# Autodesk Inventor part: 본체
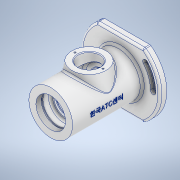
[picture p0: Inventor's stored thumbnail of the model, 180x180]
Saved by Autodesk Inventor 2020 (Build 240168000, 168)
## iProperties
Created: 2022-05
Part Number: 본체
Material: 알루미늄 6061
Document SubType Name: Modeling
Designer: Student
Density: 2.7 g/cm^3
Appearance: 알루미늄 - 평지
Mass: 694.374 g
Surface Area: 622.592 cm^2
Volume: 257.175 cm^3
Author: Student
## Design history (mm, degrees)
sketch "스케치1"
  geometry: L1 (0, 57.5)-(0, -57.5); L2 (32, 57.5)-(32, -44.5); L3 (32, -44.5)-(58, -44.5); L4 (58, -44.5)-(58, -54.5); L5 (58, -54.5)-(36, -54.5); L6 (36, -54.5)-(36, -57.5); L7 (36, -57.5)-(30, -57.5); L8 (30, -57.5)-(20, -43.5); L9 (14.596, -36.2)-(11, -36.2); L10 (11, -36.2)-(11, -33.5); L11 (11, -33.5)-(15, -33.5); L12 (15, -33.5)-(15, -28.5); L13 (15, -28.5)-(17.5, -28.5); L14 (17.5, -28.5)-(17.5, -17.5); L15 (17.5, -17.5)-(27, -17.5); L16 (27, -17.5)-(27, 20.5); L17 (27, 20.5)-(17.5, 20.5); L18 (17.5, 20.5)-(17.5, 31.5); L19 (17.5, 31.5)-(18.5, 31.5); L20 (18.5, 31.5)-(18.5, 33.25); L21 (18.5, 33.25)-(17.5, 33.25); L22 (17.5, 33.25)-(17.5, 35.5); L23 (17.5, 35.5)-(22.5, 35.5); L24 (22.5, 35.5)-(22.5, 46.5); L25 (22.5, 46.5)-(24, 46.5); L26 (24, 46.5)-(24, 49.5); L27 (24, 49.5)-(0, 49.5); L28 (32, 57.5)-(0, 57.5); L29 (14.596, -36.2)-(14.596, -42.8); L30 (14.596, -42.8)-(15, -43.5); L31 (15, -43.5)-(20, -43.5); 3 further points
  constraints: 62 end point, 21 perpendicular, 4 vertical, 2 horizontal, 2 midpoint, 2 point on line, 1 coincident, 1 horizontal alignment
  dimensions: "d0" = 115 distance of L1.start L1.end; "d1" = 64 diameter of L2 L1; "d2" = 116 diameter of L4 L1; "d3" = 72 diameter of L6 L1; "d4" = 60 diameter of L7.end L1; "d5" = 40 diameter of L8.end L1; "d6" = 22 diameter of L10 L1; "d9" = 150 deg angle of L29 L30; "d10" = 0.7 distance from line of L29.end L31; "d11" = 30 diameter of L30.end L1; "d12" = 14 distance between parallel lines of L31 L7; "d13" = 6.6 distance of L9.start L29.end; "d15" = 5 distance from line of L12.end L11; "d16" = 29 distance between parallel lines of L7 L13; "d17" = 11 distance from line of L14.end L13; "d18" = 38 distance from line of L16.end L15; "d19" = 54 diameter of L16 L1; "d20" = 30 diameter of L12 L1; "d21" = 35 diameter of L14 L1; "d22" = 35 diameter of L18 L1; "d23" = 37 diameter of L20 L1; "d24" = 11 distance between parallel lines of L19 L17; "d25" = 1.75 distance between parallel lines of L21 L19; "d26" = 4 distance between parallel lines of L23 L19; "d27" = 45 diameter of L24 L1; "d28" = 22 distance between parallel lines of L28 L23; "d29" = 3 distance between parallel lines of L27 L25; "d30" = 8 distance between parallel lines of L28 L27; "d31" = 48 diameter of L26 L1; "d32" = 13 distance between parallel lines of L3 L7; "d33" = 3 distance between parallel lines of L7 L5
revolve "회전1" sketch "스케치1" stored, may be unused: angle "d34" = 90 deg
sketch "스케치2"
  geometry: C1 r 11 at (0, 0) reference; 2 further points
  constraints: 1 coincident
hole "구멍1" sketch "스케치2" at (0, 0) diameter "d35" = 43.376; stored, may be unused: countersink angle "d39" = 90 deg, drill point angle "d41" = 0 deg; dims "d36" = 8, "d37" = 4, "d38" = 2, "d40" = 10
sketch "스케치3"
  geometry: L1 (-33.985, 47)-(33.985, 47); L2 (33.985, -47)-(-33.985, -47); L3 (0, 47)-(0, -47); A1 r 58 centre (0, 0) between (-33.985, 47) and (33.985, 47) reference; 2 further points
  constraints: 6 end point, 4 point on circle, 3 midpoint, 1 coincident, 1 horizontal, 1 parallel
  dimensions: "d42" = 94 distance between parallel lines of L2 L1
extrude "돌출1" cut sketch "스케치3" distance "d43" = 10; taper "d44" = 0 deg
sketch "스케치4"
  geometry: L1 (33.985, 47)-(-2.785, 16.146); L2 (33.985, 47)-(-14.015, 47); L3 (33.985, 47)-(70.755, 77.854); L4 (33.985, 47)-(81.985, 47); A1 r 48 centre (33.985, 47) between (-14.015, 47) and (-2.785, 16.146); A2 r 52 centre (33.985, 47) between (-18.015, 47) and (-5.849, 13.575); A3 r 44 centre (33.985, 47) between (-10.015, 47) and (0.279, 18.717); A4 r 4 centre (-14.015, 47) between (-10.015, 47) and (-18.015, 47); A5 r 4 centre (-2.785, 16.146) between (-5.849, 13.575) and (0.279, 18.717); A6 r 48 centre (33.985, 47) between (81.985, 47) and (70.755, 77.854); A7 r 52 centre (33.985, 47) between (85.985, 47) and (73.82, 80.425); A8 r 44 centre (33.985, 47) between (77.985, 47) and (67.691, 75.283); A9 r 4 centre (81.985, 47) between (77.985, 47) and (85.985, 47); A10 r 4 centre (70.755, 77.854) between (73.82, 80.425) and (67.691, 75.283); 2 further points
  constraints: 20 point on circle, 10 centre point, 8 end point, 8 tangent, 2 coincident, 1 horizontal, 1 point on line
  dimensions: "d47" = 48 radius of A1; "d48" = 40 deg angle of L2 L1; "d50" = 4 radius of A4; "d51" = 40 deg angle of L4 L3; "d52" = 4 radius of A10; "d53" = 48 radius of A6
extrude "돌출2" cut sketch "스케치4" distance "d54" = 4.4; taper "d55" = 0 deg
sketch "스케치5"
  geometry: L1 (33.985, 47)-(70.755, 77.854); L2 (33.985, 47)-(81.985, 47); L3 (33.985, 47)-(-2.785, 16.146); L4 (33.985, 47)-(-14.015, 47); C1 r 15 at (33.985, 47) reference; A1 r 48 centre (33.985, 47) between (81.985, 47) and (70.755, 77.854); A2 r 50.25 centre (33.985, 47) between (84.235, 47) and (72.479, 79.3); A3 r 45.75 centre (33.985, 47) between (79.735, 47) and (69.032, 76.408); A4 r 2.25 centre (81.985, 47) between (79.735, 47) and (84.235, 47); A5 r 2.25 centre (70.755, 77.854) between (72.479, 79.3) and (69.032, 76.408); A6 r 48 centre (33.985, 47) between (-14.015, 47) and (-2.785, 16.146); A7 r 50.25 centre (33.985, 47) between (-16.265, 47) and (-4.508, 14.7); A8 r 45.75 centre (33.985, 47) between (-11.765, 47) and (-1.061, 17.592); A9 r 2.25 centre (-14.015, 47) between (-11.765, 47) and (-16.265, 47); A10 r 2.25 centre (-2.785, 16.146) between (-4.508, 14.7) and (-1.061, 17.592); 1 further point
  constraints: 21 point on circle, 10 centre point, 8 end point, 8 tangent, 2 coincident, 1 horizontal
  dimensions: "d56" = 48 radius of A1; "d57" = 40 deg angle of L2 L1; "d58" = 2.25 radius of A5; "d59" = 40 deg angle of L4 L3; "d60" = 2.25 radius of A10; "d61" = 140 deg angle of L2 L3
extrude "돌출3" cut sketch "스케치5" distance "d62" = 5.6; taper "d63" = 0 deg
sketch "스케치6"
  geometry: C1 r 4 at (70.755, 77.854); C2 r 4 at (-2.785, 16.146); A1 r 4 centre (70.755, 77.854) between (73.82, 80.425) and (67.691, 75.283) reference; A2 r 4 centre (-14.015, 47) between (-10.015, 47) and (-18.015, 47) reference; A3 r 2.25 centre (-2.785, 16.146) between (-4.508, 14.7) and (-1.061, 17.592) reference; 3 further points
  constraints: 2 centre point, 2 coincident
extrude "돌출4" cut sketch "스케치6" distance "d64" = 5.6; taper "d65" = 0 deg
node "작업 평면1"
sketch "스케치7"
  geometry: L1 (-32, 57.5)-(32, 57.5) reference; C1 r 25 at (0, 1.5); 1 further point
  constraints: 1 centre point
  dimensions: "d67" = 25 radius of C1; "d68" = 56 distance from line of C1.centre L1
extrude "돌출5" join sketch "스케치7" stored distance "d69" = 5.6; taper "d70" = 10 deg; dims "d0" = 115, "d1" = 64, "d2" = 116, "d3" = 72, "d4" = 60, "d5" = 40, "d6" = 22, "d9" = 150 deg, "d10" = 0.7, "d11" = 30, "d12" = 14, "d13" = 6.6, "d15" = 5, "d16" = 29, "d17" = 11, "d18" = 38, "d19" = 54, "d20" = 30, "d21" = 35, "d22" = 35, "d23" = 37, "d24" = 11, "d25" = 1.75, "d26" = 4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
sketch "스케치8"
  geometry: C1 r 25 at (0, 0) reference; C2 r 16 at (0, 0); 1 further point
  constraints: 1 centre point, 1 coincident
  dimensions: "d71" = 16 radius of C2
extrude "돌출6" cut sketch "스케치8" stored distance "d72" = 5.6; taper "d73" = 0 deg
sketch "스케치9"
  geometry: L1 (27, 19)-(-27, 19) reference; L2 (27, -19)-(-27, -19) reference; C1 r 25 at (0, 0) reference; 3 further points
  constraints: 1 other
  dimensions: "d74" = 20.5 distance of C1.centre point (20.5, -0.011)
hole "구멍2" sketch "스케치9" at (20.5, -0.011) diameter "d75" = 2.459; stored, may be unused: countersink angle "d79" = 90 deg, drill point angle "d81" = 118 deg; dims "d76" = 6, "d77" = 4, "d78" = 2, "d80" = 8
node "작업 평면2"
sketch "스케치10"
  geometry: L1 (8.299, 44.594)-(8.299, -29.594); L2 (8.299, -29.594)-(-8.299, -29.594); L3 (-8.299, -29.594)-(-8.299, 44.594); L4 (-8.299, 44.594)-(8.299, 44.594); L5 (-8.299, 44.594)-(8.299, -29.594); L6 (-32, 57.5)-(32, 57.5) reference; L7 (-47, -54.5)-(47, -54.5) reference; L8 (-32, 57.5)-(-32, -44.5) reference; 2 further points
  constraints: 2 end point, 1 midpoint, 2 other
  dimensions: "d87" = 62 distance from line of L7 point (0, 7.5); "d88" = 32 distance from line of L8 point (0, 7.5)
feature "엠보싱1" sketch "스케치10" dims "d0" = 115, "d1" = 64, "d2" = 116, "d3" = 72, "d4" = 60, "d5" = 40, "d6" = 22, "d9" = 150 deg, "d10" = 0.7, "d11" = 30, "d12" = 14, "d13" = 6.6, "d15" = 5, "d16" = 29, "d17" = 11, "d18" = 38, "d19" = 54, "d20" = 30, "d21" = 35, "d22" = 35, "d23" = 37, "d24" = 11, "d25" = 1.75, "d26" = 4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
fillet "모깎기1" dims "d91" = 3
fillet "모깎기2" dims "d92" = 3
fillet "모깎기3" dims "d93" = 3
chamfer "모따기1" distance "d94" = 1; stored, may be unused: second distance "d95" = 2, angle "d96" = 45 deg
fillet "모깎기4" dims "d97" = 3
chamfer "모따기2" distance "d98" = 1; stored, may be unused: second distance "d99" = 2, angle "d100" = 45 deg
fillet "모깎기5" dims "d101" = 3
fillet "모깎기6" dims "d102" = 0.6
fillet "모깎기7" dims "d103" = 3
fillet "모깎기8" dims "d104" = 0.5
node "솔리드1"
pattern_circular "원형 패턴1" dims angle "d83" = 360 deg
node "투영된 루프1"
feature "A9D066F2-1C7D-4E18-AEED-F7BC21143FA4" dims "d35" = 43.376, "d36" = 8, "d37" = 4, "d38" = 2, "d39" = 90 deg, "d40" = 10, "d41" = 0
other parameters: "d66" = 38, "d85" = 32.5
